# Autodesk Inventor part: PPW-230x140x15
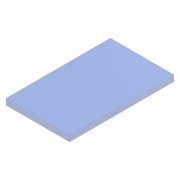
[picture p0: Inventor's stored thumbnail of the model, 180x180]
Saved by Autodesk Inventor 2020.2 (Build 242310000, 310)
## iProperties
Created: 2015-11
Part Number: PPW-230x140x15
Material: Ogólny
Document SubType Name: Modeling
Designer: F.Stasiak
Density: 1 g/cm^3
Appearance: Przezroczysty - niebieski
Catalog Web Link: www.expertbooks.pl
Manager: www.cadconsulting.pl
Company: Fabian Stasiak CAD Consulting
Author: F.Stasiak
Subject: Zbiór ćwiczeń. Autodesk Inventor 2020. Kurs Professional
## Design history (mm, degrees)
sketch "Szkic1"
  geometry: L1 (-70, 115)-(70, 115); L2 (70, 115)-(70, -115); L3 (70, -115)-(-70, -115); L4 (-70, -115)-(-70, 115); L5 (-70, 115)-(70, -115); L6 (70, 115)-(-70, -115); 1 further point
  constraints: 12 end point, 2 midpoint, 2 parallel, 1 horizontal, 1 perpendicular
  dimensions: "d0" = 140 distance of L2.end L3.end; "d1" = 230 distance of L1.end L2.end
extrude "Wyciągnięcie proste1" new body sketch "Szkic1" distance "d2" = 14; taper "d3" = 0 deg
node "Bryła1"
